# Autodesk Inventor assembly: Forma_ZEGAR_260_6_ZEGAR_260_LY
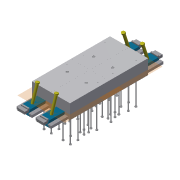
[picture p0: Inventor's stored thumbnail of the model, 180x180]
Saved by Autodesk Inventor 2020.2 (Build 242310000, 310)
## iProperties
Created: 2015-01
Part Number: Forma_ZEGAR_260_6_ZEGAR_260_LY
Document SubType Name: Assembly
Designer: F.Stasiak
Catalog Web Link: www.expertbooks.pl
Manager: www.cadconsulting.pl
Company: Fabian Stasiak CAD Consulting
Author: F.Stasiak
Subject: Zbiór ćwiczeń. Autodesk Inventor 2020. Kurs Professional
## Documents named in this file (10)
- C:\2020_Kurs_Professional\R6 Formy\Komponenty\Forma_ZEGAR_260_6_ZEGAR_260_LY.iam
- C:\2020_Kurs_Professional\R6 Formy\Komponenty\Forma_ZEGAR_260_6_ZEGAR_260_PZ.iam
- C:\2020_Kurs_Professional\R6 Formy\Komponenty\Forma_ZEGAR_260_6_ZEGAR_260_CV_2.ipt
- C:\2020_Kurs_Professional\R6 Formy\Komponenty\Forma_ZEGAR_260_6_ZEGAR_260_CV_3.ipt
- C:\2020_Kurs_Professional\R6 Formy\Komponenty\Forma_ZEGAR_260_6_ZEGAR_260_CV_4.ipt
- C:\2020_Kurs_Professional\R6 Formy\Komponenty\Forma_ZEGAR_260_6_ZEGAR_260_CV_1.ipt
- C:\2020_Kurs_Professional\R6 Formy\Komponenty\Forma_ZEGAR_260_6_ZEGAR_260_CR_2.ipt
- C:\2020_Kurs_Professional\R6 Formy\Komponenty\Forma_ZEGAR_260_6_ZEGAR_260_CR_3.ipt
- C:\2020_Kurs_Professional\R6 Formy\Komponenty\Forma_ZEGAR_260_6_ZEGAR_260_CR_4.ipt
- C:\2020_Kurs_Professional\R6 Formy\Komponenty\Forma_ZEGAR_260_6_ZEGAR_260_CR_1.ipt
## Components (12 placed, 9 different names)
1. Forma_ZEGAR_260_4_ZEGAR_260_PZ:1 [sub-assembly] — Równoległy:1, Równoległy:2, Równoległy:3, Równoległy:13, Równoległy:14, Równoległy:15, Równoległy:25, Równoległy:26, Równoległy:27, Równoległy:50, Równoległy:51, Równoległy:58, Równoległy:59, Równoległy:60
2. Forma_ZEGAR_260_4_ZEGAR_260_PZ:2 [sub-assembly] — Równoległy:4, Równoległy:5, Równoległy:6, Równoległy:16, Równoległy:17, Równoległy:18, Równoległy:28, Równoległy:29, Równoległy:30, Równoległy:52, Równoległy:53, Równoległy:61, Równoległy:62, Równoległy:63
3. Forma_ZEGAR_260_4_ZEGAR_260_PZ:3 [sub-assembly] — Równoległy:7, Równoległy:8, Równoległy:9, Równoległy:19, Równoległy:20, Równoległy:21, Równoległy:31, Równoległy:32, Równoległy:33, Równoległy:54, Równoległy:55, Równoległy:64, Równoległy:65, Równoległy:66
4. Forma_ZEGAR_260_4_ZEGAR_260_PZ:4 [sub-assembly] — Równoległy:10, Równoległy:11, Równoległy:12, Równoległy:22, Równoległy:23, Równoległy:24, Równoległy:34, Równoległy:35, Równoległy:36, Równoległy:56, Równoległy:57, Równoległy:67, Równoległy:68, Równoległy:69
5. Forma_ZEGAR_260_4_ZEGAR_260_CV_1:1 — Równoległy:13, Równoległy:14, Równoległy:15, Równoległy:58, Równoległy:59, Równoległy:60
6. Forma_ZEGAR_260_4_ZEGAR_260_CV_2:1 — Równoległy:16, Równoległy:17, Równoległy:18, Równoległy:61, Równoległy:62, Równoległy:63
7. Forma_ZEGAR_260_4_ZEGAR_260_CV_3:1 — Równoległy:19, Równoległy:20, Równoległy:21, Równoległy:64, Równoległy:65, Równoległy:66
8. Forma_ZEGAR_260_4_ZEGAR_260_CV_4:1 — Równoległy:22, Równoległy:23, Równoległy:24, Równoległy:67, Równoległy:68, Równoległy:69
9. Forma_ZEGAR_260_4_ZEGAR_260_CR_1:1 — Równoległy:25, Równoległy:26, Równoległy:27, Równoległy:50, Równoległy:51
10. Forma_ZEGAR_260_4_ZEGAR_260_CR_2:1 — Równoległy:28, Równoległy:29, Równoległy:30, Równoległy:52, Równoległy:53
11. Forma_ZEGAR_260_4_ZEGAR_260_CR_3:1 — Równoległy:31, Równoległy:32, Równoległy:33, Równoległy:54, Równoległy:55
12. Forma_ZEGAR_260_4_ZEGAR_260_CR_4:1 — Równoległy:34, Równoległy:35, Równoległy:36, Równoległy:56, Równoległy:57
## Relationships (56: Flush 56)
- Równoległy:1 [Flush]: Forma_ZEGAR_260_4_ZEGAR_260_PZ:1
- Równoległy:2 [Flush]: Forma_ZEGAR_260_4_ZEGAR_260_PZ:1
- Równoległy:3 [Flush]: Forma_ZEGAR_260_4_ZEGAR_260_PZ:1
- Równoległy:4 [Flush]: Forma_ZEGAR_260_4_ZEGAR_260_PZ:2
- Równoległy:5 [Flush]: Forma_ZEGAR_260_4_ZEGAR_260_PZ:2
- Równoległy:6 [Flush]: Forma_ZEGAR_260_4_ZEGAR_260_PZ:2
- Równoległy:7 [Flush]: Forma_ZEGAR_260_4_ZEGAR_260_PZ:3
- Równoległy:8 [Flush]: Forma_ZEGAR_260_4_ZEGAR_260_PZ:3
- Równoległy:9 [Flush]: Forma_ZEGAR_260_4_ZEGAR_260_PZ:3
- Równoległy:10 [Flush]: Forma_ZEGAR_260_4_ZEGAR_260_PZ:4
- Równoległy:11 [Flush]: Forma_ZEGAR_260_4_ZEGAR_260_PZ:4
- Równoległy:12 [Flush]: Forma_ZEGAR_260_4_ZEGAR_260_PZ:4
- Równoległy:13 [Flush]: Forma_ZEGAR_260_4_ZEGAR_260_PZ:1 ↔ Forma_ZEGAR_260_4_ZEGAR_260_CV_1:1
- Równoległy:14 [Flush]: Forma_ZEGAR_260_4_ZEGAR_260_PZ:1 ↔ Forma_ZEGAR_260_4_ZEGAR_260_CV_1:1
- Równoległy:15 [Flush]: Forma_ZEGAR_260_4_ZEGAR_260_PZ:1 ↔ Forma_ZEGAR_260_4_ZEGAR_260_CV_1:1
- Równoległy:16 [Flush]: Forma_ZEGAR_260_4_ZEGAR_260_PZ:2 ↔ Forma_ZEGAR_260_4_ZEGAR_260_CV_2:1
- Równoległy:17 [Flush]: Forma_ZEGAR_260_4_ZEGAR_260_PZ:2 ↔ Forma_ZEGAR_260_4_ZEGAR_260_CV_2:1
- Równoległy:18 [Flush]: Forma_ZEGAR_260_4_ZEGAR_260_PZ:2 ↔ Forma_ZEGAR_260_4_ZEGAR_260_CV_2:1
- Równoległy:19 [Flush]: Forma_ZEGAR_260_4_ZEGAR_260_PZ:3 ↔ Forma_ZEGAR_260_4_ZEGAR_260_CV_3:1
- Równoległy:20 [Flush]: Forma_ZEGAR_260_4_ZEGAR_260_PZ:3 ↔ Forma_ZEGAR_260_4_ZEGAR_260_CV_3:1
- Równoległy:21 [Flush]: Forma_ZEGAR_260_4_ZEGAR_260_PZ:3 ↔ Forma_ZEGAR_260_4_ZEGAR_260_CV_3:1
- Równoległy:22 [Flush]: Forma_ZEGAR_260_4_ZEGAR_260_PZ:4 ↔ Forma_ZEGAR_260_4_ZEGAR_260_CV_4:1
- Równoległy:23 [Flush]: Forma_ZEGAR_260_4_ZEGAR_260_PZ:4 ↔ Forma_ZEGAR_260_4_ZEGAR_260_CV_4:1
- Równoległy:24 [Flush]: Forma_ZEGAR_260_4_ZEGAR_260_PZ:4 ↔ Forma_ZEGAR_260_4_ZEGAR_260_CV_4:1
- Równoległy:25 [Flush]: Forma_ZEGAR_260_4_ZEGAR_260_PZ:1 ↔ Forma_ZEGAR_260_4_ZEGAR_260_CR_1:1
- Równoległy:26 [Flush]: Forma_ZEGAR_260_4_ZEGAR_260_PZ:1 ↔ Forma_ZEGAR_260_4_ZEGAR_260_CR_1:1
- Równoległy:27 [Flush]: Forma_ZEGAR_260_4_ZEGAR_260_PZ:1 ↔ Forma_ZEGAR_260_4_ZEGAR_260_CR_1:1
- Równoległy:28 [Flush]: Forma_ZEGAR_260_4_ZEGAR_260_PZ:2 ↔ Forma_ZEGAR_260_4_ZEGAR_260_CR_2:1
- Równoległy:29 [Flush]: Forma_ZEGAR_260_4_ZEGAR_260_PZ:2 ↔ Forma_ZEGAR_260_4_ZEGAR_260_CR_2:1
- Równoległy:30 [Flush]: Forma_ZEGAR_260_4_ZEGAR_260_PZ:2 ↔ Forma_ZEGAR_260_4_ZEGAR_260_CR_2:1
- Równoległy:31 [Flush]: Forma_ZEGAR_260_4_ZEGAR_260_PZ:3 ↔ Forma_ZEGAR_260_4_ZEGAR_260_CR_3:1
- Równoległy:32 [Flush]: Forma_ZEGAR_260_4_ZEGAR_260_PZ:3 ↔ Forma_ZEGAR_260_4_ZEGAR_260_CR_3:1
- Równoległy:33 [Flush]: Forma_ZEGAR_260_4_ZEGAR_260_PZ:3 ↔ Forma_ZEGAR_260_4_ZEGAR_260_CR_3:1
- Równoległy:34 [Flush]: Forma_ZEGAR_260_4_ZEGAR_260_PZ:4 ↔ Forma_ZEGAR_260_4_ZEGAR_260_CR_4:1
- Równoległy:35 [Flush]: Forma_ZEGAR_260_4_ZEGAR_260_PZ:4 ↔ Forma_ZEGAR_260_4_ZEGAR_260_CR_4:1
- Równoległy:36 [Flush]: Forma_ZEGAR_260_4_ZEGAR_260_PZ:4 ↔ Forma_ZEGAR_260_4_ZEGAR_260_CR_4:1
- Równoległy:50 [Flush]: Forma_ZEGAR_260_4_ZEGAR_260_PZ:1 ↔ Forma_ZEGAR_260_4_ZEGAR_260_CR_1:1
- Równoległy:51 [Flush]: Forma_ZEGAR_260_4_ZEGAR_260_PZ:1 ↔ Forma_ZEGAR_260_4_ZEGAR_260_CR_1:1
- Równoległy:52 [Flush]: Forma_ZEGAR_260_4_ZEGAR_260_PZ:2 ↔ Forma_ZEGAR_260_4_ZEGAR_260_CR_2:1
- Równoległy:53 [Flush]: Forma_ZEGAR_260_4_ZEGAR_260_PZ:2 ↔ Forma_ZEGAR_260_4_ZEGAR_260_CR_2:1
- Równoległy:54 [Flush]: Forma_ZEGAR_260_4_ZEGAR_260_PZ:3 ↔ Forma_ZEGAR_260_4_ZEGAR_260_CR_3:1
- Równoległy:55 [Flush]: Forma_ZEGAR_260_4_ZEGAR_260_PZ:3 ↔ Forma_ZEGAR_260_4_ZEGAR_260_CR_3:1
- Równoległy:56 [Flush]: Forma_ZEGAR_260_4_ZEGAR_260_PZ:4 ↔ Forma_ZEGAR_260_4_ZEGAR_260_CR_4:1
- Równoległy:57 [Flush]: Forma_ZEGAR_260_4_ZEGAR_260_PZ:4 ↔ Forma_ZEGAR_260_4_ZEGAR_260_CR_4:1
- Równoległy:58 [Flush]: Forma_ZEGAR_260_4_ZEGAR_260_PZ:1 ↔ Forma_ZEGAR_260_4_ZEGAR_260_CV_1:1
- Równoległy:59 [Flush]: Forma_ZEGAR_260_4_ZEGAR_260_PZ:1 ↔ Forma_ZEGAR_260_4_ZEGAR_260_CV_1:1
- Równoległy:60 [Flush]: Forma_ZEGAR_260_4_ZEGAR_260_PZ:1 ↔ Forma_ZEGAR_260_4_ZEGAR_260_CV_1:1
- Równoległy:61 [Flush]: Forma_ZEGAR_260_4_ZEGAR_260_PZ:2 ↔ Forma_ZEGAR_260_4_ZEGAR_260_CV_2:1
- Równoległy:62 [Flush]: Forma_ZEGAR_260_4_ZEGAR_260_PZ:2 ↔ Forma_ZEGAR_260_4_ZEGAR_260_CV_2:1
- Równoległy:63 [Flush]: Forma_ZEGAR_260_4_ZEGAR_260_PZ:2 ↔ Forma_ZEGAR_260_4_ZEGAR_260_CV_2:1
- Równoległy:64 [Flush]: Forma_ZEGAR_260_4_ZEGAR_260_PZ:3 ↔ Forma_ZEGAR_260_4_ZEGAR_260_CV_3:1
- Równoległy:65 [Flush]: Forma_ZEGAR_260_4_ZEGAR_260_PZ:3 ↔ Forma_ZEGAR_260_4_ZEGAR_260_CV_3:1
- Równoległy:66 [Flush]: Forma_ZEGAR_260_4_ZEGAR_260_PZ:3 ↔ Forma_ZEGAR_260_4_ZEGAR_260_CV_3:1
- Równoległy:67 [Flush]: Forma_ZEGAR_260_4_ZEGAR_260_PZ:4 ↔ Forma_ZEGAR_260_4_ZEGAR_260_CV_4:1
- Równoległy:68 [Flush]: Forma_ZEGAR_260_4_ZEGAR_260_PZ:4 ↔ Forma_ZEGAR_260_4_ZEGAR_260_CV_4:1
- Równoległy:69 [Flush]: Forma_ZEGAR_260_4_ZEGAR_260_PZ:4 ↔ Forma_ZEGAR_260_4_ZEGAR_260_CV_4:1
